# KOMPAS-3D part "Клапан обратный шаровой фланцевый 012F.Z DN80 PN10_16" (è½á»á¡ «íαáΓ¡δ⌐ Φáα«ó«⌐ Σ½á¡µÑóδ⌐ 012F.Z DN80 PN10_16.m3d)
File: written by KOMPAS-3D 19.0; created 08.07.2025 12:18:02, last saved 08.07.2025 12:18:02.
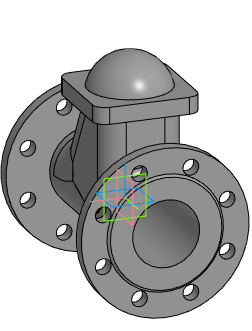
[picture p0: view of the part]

Document properties: Полное имя файла: E:\Dendor Работа Сачек\3D для проектировщиков\5.3 Тип 012F, 012F.Z Клапан обратный шаровой фланцевый\stp_Клапан обратный шаровой фланцевый 012F.Z PN10_16\Клапан обратный шаровой фланцевый 012F.Z DN80 PN10_16.m3d

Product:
- Part/product: Клапан обратный шаровой фланцевый 012F.Z DN80 PN10_16

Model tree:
1. Операция без истории:1  (labels: Клапан обратный шаровой фланцевый 012F.Z DN80 PN10_16)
